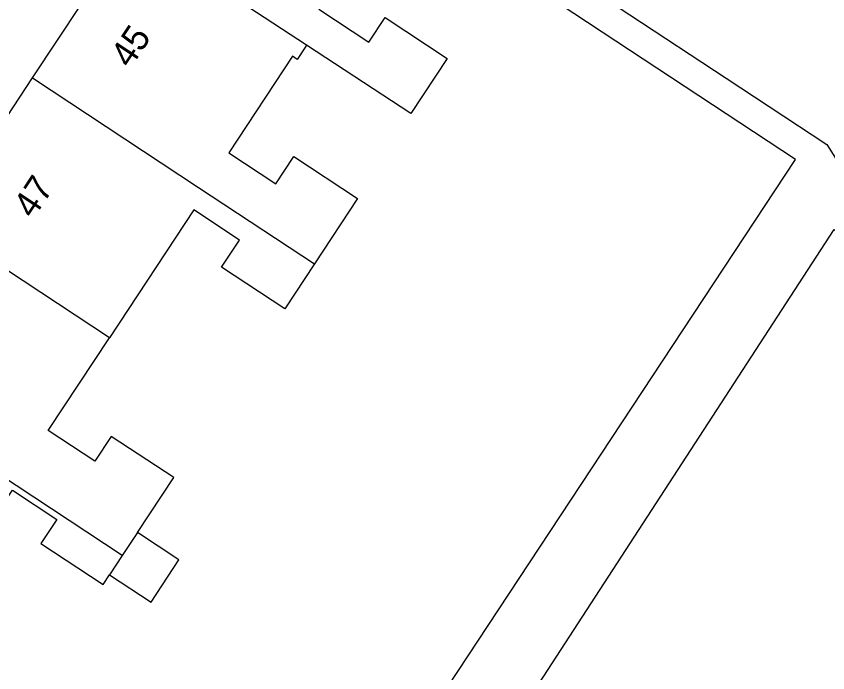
# Model space of a CAD drawing. Extents: x 159280 to 160375, y 384531 to 385872.
# Drawn here: x 160014.71 to 160045.8, y 384800.04 to 384825.21 of the extents above; entities that cross this region are included whole.
import ezdxf

# ---------------------------------------------------------------- set-up
doc = ezdxf.new("R2010")
doc.units = 0
for name, color, linetype in [('IMGEO_Pand', 7, 'Continuous'), ('IMGEO_Pand_nummerreeks', 7, 'Continuous'), ('IMGEO_Voetpad_open', 7, 'Continuous')]:
    doc.layers.add(name, color=color, linetype=linetype)

msp = doc.modelspace()

# ---------------------------------------------------------------- linework, layer by layer
at = {"layer": 'IMGEO_Pand'}
for points in [[(160029.19, 384829.86), (160026.299, 384825.476), (160028.212, 384824.214), (160028.84, 384825.166), (160031.224, 384823.593), (160029.831, 384821.482), (160025.832, 384824.102)], [(160015.335, 384822.844), (160019.082, 384828.524)], [(160025.832, 384824.102), (160019.082, 384828.524)], [(160025.832, 384824.102), (160025.765, 384824), (160025.47, 384823.553), (160025.289, 384823.672), (160022.85, 384819.976), (160024.66, 384818.782), (160025.35, 384819.828), (160027.784, 384818.223), (160026.133, 384815.721)], [(160011.647, 384817.255), (160015.335, 384822.844)], [(160015.335, 384822.844), (160021.696, 384818.648), (160026.133, 384815.721)], [(160026.133, 384815.721), (160024.996, 384813.998), (160022.576, 384815.594), (160023.26, 384816.631), (160021.511, 384817.785), (160018.277, 384812.882)], [(160018.277, 384812.882), (160011.647, 384817.255)], [(160019.354, 384805.424), (160020.74, 384807.524), (160018.348, 384809.102), (160017.723, 384808.154), (160015.935, 384809.333), (160018.277, 384812.882)], [(160018.769, 384804.537), (160007.96, 384811.666)], [(160010.982, 384801.651), (160014.564, 384807.039), (160016.262, 384805.919), (160015.654, 384804.997), (160018.036, 384803.426), (160018.285, 384803.804)], [(160018.285, 384803.804), (160019.875, 384802.755), (160020.943, 384804.375), (160019.354, 384805.424)], [(160019.354, 384805.424), (160018.769, 384804.537)], [(160018.769, 384804.537), (160018.285, 384803.804)]]:
    msp.add_lwpolyline(points, dxfattribs=at)
at = {"layer": 'IMGEO_Voetpad_open'}
for points in [[(160019.768, 384837.41), (160041.911, 384822.833), (160045.771, 384820.292), (160046.945, 384818.444), (160069.13, 384803.734)], [(159986.258, 384735.984), (160003.921, 384733.4), (160014.299, 384731.886), (160015.76, 384743.962), (160020.308, 384781.549), (160021.355, 384784.522), (160035.962, 384806.663), (160044.571, 384819.713), (160029.19, 384829.86)], [(160032.071, 384795.537), (160046.054, 384817.032), (160061.594, 384806.958)]]:
    msp.add_lwpolyline(points, dxfattribs=at)

# ---------------------------------------------------------------- texts
at = {"layer": 'IMGEO_Pand_nummerreeks'}
for s, rotation, p in [('45', 56.4249, (160019.082, 384823.177)), ('47', 56.4221, (160015.358, 384817.41))]:
    msp.add_text(s, height=1, rotation=rotation, dxfattribs=at).set_placement(p)

doc.saveas('drawing.dxf')
